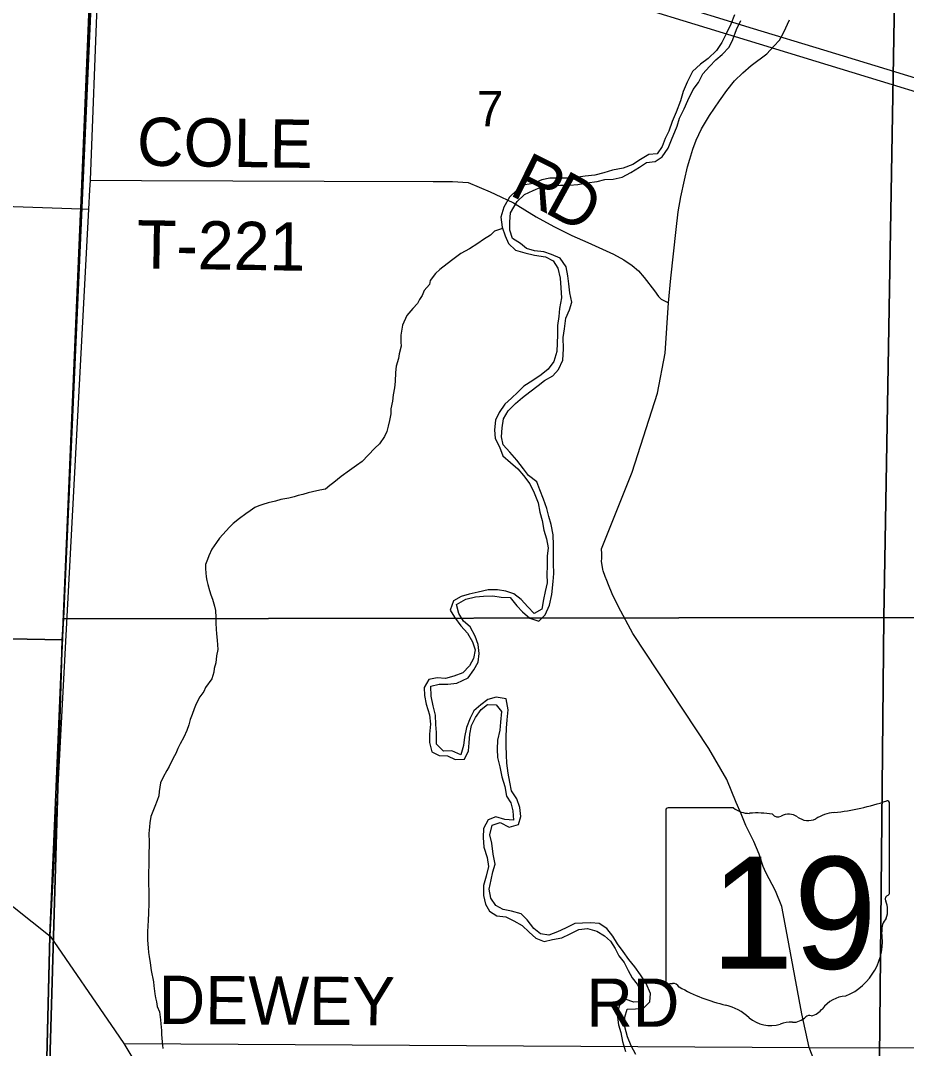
# Model space of a CAD drawing. Extents: x 36.7 to 70.7, y 0 to 22.
# Drawn here: x 41.231 to 42.275, y 17.404 to 18.615 of the extents above; entities that cross this region are included whole.
import ezdxf

# ---------------------------------------------------------------- set-up
doc = ezdxf.new("R2010")
doc.units = 0
for name, color, linetype in [('GM_X_County_Road', 7, 'Continuous'), ('GM_X_County_Road_Text', 7, 'Continuous'), ('GM_X_Minor_River', 7, 'Continuous'), ('GM_X_Rail_Line', 7, 'Continuous'), ('GM_X_Section', 7, 'Continuous'), ('GM_X_Section_Text', 7, 'Continuous'), ('GM_X_State_Location', 7, 'Continuous'), ('GM_X_State_Route', 7, 'Continuous'), ('GM_X_State_Shield', 7, 'Continuous'), ('GM_X_Township_Road', 7, 'Continuous'), ('GM_X_Township_Road_Text', 7, 'Continuous')]:
    doc.layers.add(name, color=color, linetype=linetype)

msp = doc.modelspace()

# ---------------------------------------------------------------- linework, layer by layer
at = {"layer": 'GM_X_County_Road'}
for p, q in [((41.3138, 18.4272), (41.3291, 18.8232)), ((41.3132, 18.4157), (41.3138, 18.4272)), ((41.3119, 18.3928), (41.3132, 18.4157)), ((41.2664, 17.5366), (41.3119, 18.3928)), ((41.2501, 16.8809), (41.2664, 17.5366)), ((41.3531, 17.4104), (42.1609, 17.4056))]:
    msp.add_line(p, q, dxfattribs=at)
for points in [[(40.8318, 18.4101), (40.8294, 18.29), (40.8266, 18.1856), (40.8334, 18.07), (40.8364, 18.021), (40.8467, 17.9741), (40.9906, 17.7663), (41.0943, 17.6731), (41.2664, 17.5366)], [(41.2664, 17.5366), (41.3428, 17.4253), (41.3531, 17.4104)], [(41.3531, 17.4104), (41.5942, 17.0098), (41.7249, 16.7795), (41.7442, 16.7267), (41.7621, 16.6558), (41.8308, 16.4207)], [(42.1609, 17.4056), (42.5156, 17.4053), (43.2502, 17.4045)]]:
    msp.add_lwpolyline(points, dxfattribs=at)
at = {"layer": 'GM_X_Minor_River'}
for points in [[(42.0726, 18.6219), (42.0685, 18.6106), (42.0633, 18.6001), (42.0577, 18.5893), (42.0514, 18.5796), (42.0417, 18.5703), (42.0328, 18.5637), (42.0234, 18.5549), (42.017, 18.5425), (42.0122, 18.5313), (42.0092, 18.5204), (42.0039, 18.5072), (41.9991, 18.4963), (41.9953, 18.4847), (41.9909, 18.4761), (41.9873, 18.4667)], [(41.8787, 18.2942), (41.8775, 18.3049), (41.8762, 18.3144), (41.8742, 18.3251), (41.8673, 18.3352), (41.8572, 18.3396), (41.8482, 18.3425), (41.8372, 18.344), (41.8278, 18.3465), (41.8204, 18.3524), (41.811, 18.3584), (41.8079, 18.3683), (41.8078, 18.3778), (41.8088, 18.3884), (41.8168, 18.4019), (41.8253, 18.41), (41.8353, 18.415), (41.8445, 18.4186), (41.8544, 18.4202), (41.8677, 18.421), (41.8783, 18.4211), (41.8882, 18.4219), (41.8989, 18.4239), (41.9107, 18.4255), (41.9199, 18.4279), (41.9297, 18.4284), (41.9404, 18.4307), (41.9504, 18.4362), (41.9608, 18.4423), (41.9689, 18.4478), (41.9792, 18.449), (41.9873, 18.4545), (41.9944, 18.4646), (41.9985, 18.4747), (42.005, 18.4905), (42.0079, 18.4999), (42.0135, 18.5111), (42.0179, 18.5209), (42.024, 18.534), (42.0303, 18.5422), (42.0355, 18.5523), (42.0433, 18.5608), (42.0507, 18.5686), (42.0581, 18.5752), (42.0663, 18.5837), (42.0707, 18.5927), (42.0752, 18.6043), (42.08, 18.6152)], [(41.9873, 18.4667), (41.9817, 18.4581), (41.9718, 18.4572), (41.9618, 18.4514), (41.953, 18.4456), (41.9415, 18.4413), (41.9289, 18.439), (41.9186, 18.4355), (41.9082, 18.4331), (41.8968, 18.4319), (41.8858, 18.4303), (41.8763, 18.4295), (41.8664, 18.4294), (41.8551, 18.4293), (41.8455, 18.4273), (41.8359, 18.423), (41.8256, 18.4214), (41.8164, 18.4152), (41.8074, 18.4071), (41.801, 18.3951), (41.7973, 18.3834), (41.7989, 18.3716), (41.8024, 18.3616), (41.8063, 18.3524), (41.8148, 18.3446), (41.8257, 18.3413), (41.8371, 18.3387), (41.8499, 18.3368), (41.8592, 18.332), (41.8647, 18.3235), (41.8674, 18.3116), (41.8682, 18.3002), (41.8687, 18.2884), (41.8664, 18.276), (41.8658, 18.2665), (41.864, 18.2559), (41.8641, 18.2449), (41.8638, 18.235), (41.8632, 18.2252), (41.8598, 18.2135), (41.8531, 18.2046), (41.845, 18.1976), (41.8349, 18.191), (41.8245, 18.1845), (41.8175, 18.1775), (41.8101, 18.1701), (41.802, 18.1631), (41.7956, 18.1534), (41.7912, 18.1444), (41.7898, 18.133), (41.7906, 18.1228), (41.7957, 18.1128), (41.7996, 18.1024), (41.8088, 18.0946), (41.8173, 18.0871), (41.824, 18.0793), (41.8316, 18.0693), (41.8367, 18.0589), (41.8413, 18.047), (41.8433, 18.0359), (41.846, 18.0263), (41.848, 18.0149), (41.8511, 18.0046), (41.8531, 17.9942), (41.8521, 17.9844), (41.8518, 17.973), (41.8515, 17.9628), (41.852, 17.9529), (41.8498, 17.9427), (41.8477, 17.9333), (41.8455, 17.9219), (41.8366, 17.9165), (41.8292, 17.9247), (41.8215, 17.9332), (41.8126, 17.9399), (41.8032, 17.9428), (41.7934, 17.9446), (41.7824, 17.9446), (41.7706, 17.9418), (41.7599, 17.9395), (41.7507, 17.9367)], [(41.7994, 18.3701), (41.7899, 18.3671), (41.7853, 18.3622), (41.7769, 18.357), (41.7704, 18.3525), (41.7604, 18.3461), (41.7501, 18.3406), (41.7391, 18.3323), (41.7253, 18.3218), (41.7203, 18.317), (41.7141, 18.3087), (41.7133, 18.3041), (41.7072, 18.297), (41.7048, 18.2913), (41.7017, 18.2864), (41.699, 18.2819), (41.6936, 18.2759), (41.6867, 18.2676), (41.6813, 18.2563), (41.6804, 18.2491), (41.6796, 18.2445), (41.6795, 18.2362), (41.6799, 18.2316), (41.6775, 18.2225), (41.6767, 18.2172), (41.6739, 18.2081), (41.6734, 18.2006), (41.6729, 18.1899), (41.6721, 18.1824), (41.6705, 18.1744), (41.6696, 18.1668), (41.6676, 18.1577), (41.6676, 18.1517), (41.6663, 18.1441), (41.6647, 18.1373), (41.6632, 18.1312), (41.6604, 18.1252), (41.6543, 18.1165), (41.6489, 18.1116), (41.6412, 18.103), (41.6339, 18.0958), (41.6274, 18.091), (41.619, 18.085), (41.6091, 18.0779), (41.6006, 18.0711), (41.5957, 18.0674), (41.5907, 18.0633), (41.5842, 18.0618), (41.5755, 18.06), (41.5705, 18.0589), (41.5641, 18.0567), (41.5584, 18.0557), (41.5538, 18.0542), (41.5477, 18.0527), (41.5382, 18.0509), (41.5317, 18.0491), (41.523, 18.0469), (41.5169, 18.0451), (41.5123, 18.0436), (41.5074, 18.0414), (41.502, 18.0377), (41.497, 18.0339), (41.4894, 18.0287), (41.4821, 18.0227), (41.4775, 18.0182), (41.466, 18.0054), (41.4625, 18.0005), (41.4567, 17.9926), (41.4532, 17.9847), (41.4517, 17.9801), (41.4493, 17.9745), (41.4493, 17.9692), (41.4503, 17.96), (41.451, 17.9555), (41.4521, 17.9509), (41.4539, 17.9437), (41.4557, 17.9387), (41.4576, 17.9334), (41.4601, 17.9254), (41.4612, 17.9201), (41.4615, 17.9121), (41.4614, 17.9053), (41.4621, 17.8984), (41.4624, 17.8927), (41.4631, 17.8851), (41.4637, 17.8741), (41.4625, 17.8669), (41.4617, 17.8586), (41.4597, 17.8521), (41.4593, 17.8476), (41.4569, 17.8396), (41.4492, 17.8295), (41.4472, 17.8249), (41.4426, 17.8185), (41.4383, 17.8102), (41.436, 17.8046), (41.4336, 17.7978), (41.4313, 17.7917), (41.4297, 17.7857), (41.4274, 17.7789), (41.4239, 17.7709)], [(41.7884, 17.6331), (41.7868, 17.6464), (41.7844, 17.656), (41.787, 17.6673), (41.7966, 17.6704), (41.807, 17.6652), (41.8181, 17.6683), (41.821, 17.6777), (41.8198, 17.6884), (41.8163, 17.6984), (41.8101, 17.708), (41.8081, 17.718), (41.8061, 17.7286), (41.8045, 17.7404), (41.804, 17.75), (41.8036, 17.7614), (41.8035, 17.7709), (41.8041, 17.7815), (41.8048, 17.7913), (41.8062, 17.8034), (41.8035, 17.816), (41.7919, 17.8182), (41.7819, 17.8155), (41.7738, 17.8093), (41.7656, 17.8019), (41.7612, 17.7933), (41.7571, 17.7824), (41.7545, 17.7711), (41.7535, 17.7612), (41.7502, 17.7503), (41.7397, 17.7548), (41.7298, 17.7546), (41.7217, 17.7628), (41.7217, 17.7765), (41.7208, 17.786), (41.7204, 17.7971), (41.7176, 17.8081), (41.7153, 17.8192), (41.7148, 17.831), (41.7248, 17.8334), (41.735, 17.8335), (41.7457, 17.8347), (41.7587, 17.8408), (41.7654, 17.8505), (41.7706, 17.8595), (41.772, 17.8697), (41.7708, 17.88), (41.7673, 17.8899), (41.7611, 17.9011), (41.7533, 17.9078), (41.7479, 17.9166), (41.7451, 17.9274), (41.7563, 17.9335), (41.7674, 17.9362), (41.7769, 17.9371), (41.7879, 17.9376), (41.7977, 17.9358), (41.8083, 17.9355), (41.8164, 17.9258), (41.823, 17.9188), (41.8315, 17.9113), (41.8421, 17.9076), (41.8498, 17.915), (41.8547, 17.9266), (41.8573, 17.9391), (41.8589, 17.9542), (41.8599, 17.9637), (41.8594, 17.9755), (41.8594, 17.9865), (41.8593, 17.9971), (41.8592, 18.0093), (41.8565, 18.0215), (41.8541, 18.031), (41.8517, 18.0402), (41.8475, 18.0514), (41.8432, 18.0625), (41.8397, 18.0717), (41.83, 18.0792), (41.8242, 18.0869), (41.8161, 18.0974), (41.808, 18.1067), (41.8003, 18.1153), (41.7983, 18.1248), (41.7989, 18.1355), (41.8004, 18.146), (41.8059, 18.1554), (41.8145, 18.1639), (41.823, 18.1712), (41.8316, 18.1778), (41.8412, 18.1852), (41.849, 18.191), (41.8586, 18.1965), (41.8653, 18.2039), (41.8705, 18.2151), (41.8712, 18.2284), (41.8708, 18.2417), (41.8722, 18.2519), (41.8741, 18.2644), (41.8782, 18.2745), (41.8811, 18.2835), (41.8787, 18.2942)], [(41.7507, 17.9367), (41.7415, 17.9316), (41.7378, 17.9207), (41.7428, 17.9122), (41.7501, 17.9022), (41.7579, 17.8936), (41.764, 17.8832), (41.7672, 17.874), (41.765, 17.8638), (41.7606, 17.8552), (41.7524, 17.847), (41.7421, 17.8428), (41.7321, 17.84), (41.7223, 17.841), (41.7124, 17.839), (41.7072, 17.8297), (41.7073, 17.8202), (41.7093, 17.8099), (41.7132, 17.7973), (41.7144, 17.7862), (41.7133, 17.7745), (41.7134, 17.7646), (41.7162, 17.7539), (41.7248, 17.7495), (41.7346, 17.7492), (41.7436, 17.7448), (41.7546, 17.7452), (41.7594, 17.755), (41.7601, 17.7645), (41.7607, 17.7747), (41.7629, 17.7849), (41.7677, 17.7942), (41.774, 17.8036), (41.7818, 17.8094), (41.792, 17.8091), (41.7982, 17.8014), (41.7971, 17.7889), (41.7961, 17.7794), (41.7935, 17.7677), (41.7929, 17.7571), (41.7933, 17.7472), (41.7961, 17.7361), (41.7984, 17.7243), (41.8019, 17.7128), (41.8039, 17.7017), (41.809, 17.6936), (41.8117, 17.6844), (41.8122, 17.6734), (41.802, 17.6741), (41.7914, 17.6774), (41.7826, 17.6735), (41.777, 17.6634), (41.7764, 17.6528), (41.7772, 17.6413), (41.7814, 17.6295), (41.783, 17.6188), (41.7801, 17.6075), (41.7771, 17.5962), (41.7768, 17.5844), (41.7792, 17.5745), (41.7839, 17.566), (41.7925, 17.5608), (41.8034, 17.5594), (41.8128, 17.5546), (41.8225, 17.5494), (41.8306, 17.5412), (41.8388, 17.5345), (41.8485, 17.5304), (41.8584, 17.5328), (41.8691, 17.5348), (41.8791, 17.5395), (41.8891, 17.5445), (41.8994, 17.5457), (41.9103, 17.5424), (41.9196, 17.5372), (41.9266, 17.5306), (41.9321, 17.5221), (41.9364, 17.5136), (41.9426, 17.5058), (41.9473, 17.4962), (41.952, 17.4877), (41.9579, 17.48), (41.9633, 17.4703), (41.9645, 17.4593), (41.9539, 17.4588), (41.9438, 17.4625), (41.9367, 17.4547), (41.9345, 17.4445), (41.9361, 17.4323), (41.9389, 17.4232), (41.9409, 17.4125), (41.9444, 17.401)], [(41.4239, 17.7709), (41.4196, 17.763), (41.4169, 17.7577), (41.4142, 17.752), (41.4114, 17.7464), (41.4064, 17.7366), (41.4037, 17.7317), (41.3994, 17.7241), (41.3963, 17.7173), (41.3947, 17.7071), (41.3942, 17.7018), (41.3923, 17.6965), (41.3895, 17.6893), (41.3849, 17.6776), (41.3836, 17.67), (41.3832, 17.6655), (41.3827, 17.6575), (41.383, 17.6472), (41.3829, 17.6427), (41.3825, 17.6351), (41.382, 17.5968), (41.3824, 17.5911), (41.3827, 17.5842), (41.3825, 17.5744), (41.3821, 17.5649), (41.3819, 17.5543), (41.3815, 17.5497), (41.381, 17.541), (41.3809, 17.5319), (41.3816, 17.5231), (41.3823, 17.5174), (41.383, 17.5129), (41.384, 17.5053), (41.3854, 17.4961), (41.3879, 17.4828), (41.3886, 17.4783), (41.3897, 17.4688), (41.3904, 17.4642), (41.3915, 17.4593), (41.3925, 17.4539), (41.3951, 17.4475), (41.3965, 17.438), (41.3969, 17.4334), (41.3975, 17.4254), (41.3975, 17.4209), (41.3981, 17.4121), (41.3992, 17.4045)], [(41.854, 17.5379), (41.8442, 17.5393), (41.8364, 17.5456), (41.8284, 17.556), (41.8213, 17.5631), (41.81, 17.566), (41.8002, 17.5682), (41.7913, 17.5726), (41.7854, 17.5815), (41.7838, 17.5922), (41.786, 17.6031), (41.7878, 17.6126), (41.7907, 17.6216), (41.7884, 17.6331)], [(41.9564, 17.3972), (41.951, 17.4076), (41.9467, 17.418), (41.9436, 17.4299), (41.9436, 17.4413), (41.9461, 17.4507), (41.956, 17.4512), (41.9654, 17.4517), (41.9729, 17.4594), (41.9739, 17.4693), (41.9685, 17.4808), (41.962, 17.4912), (41.9554, 17.5005), (41.9484, 17.5091), (41.9415, 17.5188), (41.9349, 17.5277), (41.9295, 17.5366), (41.9221, 17.5459), (41.9132, 17.5514), (41.9033, 17.5525), (41.8938, 17.552), (41.8844, 17.5515), (41.8736, 17.5461), (41.864, 17.5418), (41.854, 17.5379)]]:
    msp.add_lwpolyline(points, dxfattribs=at)
at = {"layer": 'GM_X_Rail_Line'}
for points in [[(39.4351, 19.5275), (39.5072, 19.4857), (39.6526, 19.4084), (39.8435, 19.3143), (39.9823, 19.2538), (40.1053, 19.2054), (40.2394, 19.1588), (40.707, 19.0117), (41.5752, 18.749), (42.4154, 18.492), (43.2547, 18.2349), (44.5058, 17.8517), (44.9515, 17.7199), (45.506, 17.5551), (45.5934, 17.5283)], [(40.4184, 19.1184), (40.5342, 19.0828), (40.5644, 19.0736), (40.633, 19.0526), (40.7242, 19.0248), (40.8662, 18.9816), (41.0703, 18.9191), (41.1118, 18.9063), (41.2352, 18.8682), (41.3301, 18.8394), (41.5595, 18.7692), (41.7245, 18.7187), (41.8299, 18.6867), (41.9106, 18.662), (41.99, 18.6377), (42.0947, 18.6058), (42.1775, 18.5805), (42.2523, 18.5576), (42.4612, 18.4939)]]:
    msp.add_lwpolyline(points, dxfattribs=at)
at = {"layer": 'GM_X_Section'}
for points in [[(41.3255, 18.8876), (41.2819, 17.9105), (41.2806, 17.8858), (40.1915, 17.9066), (40.2272, 18.9664)], [(42.2659, 18.914), (42.2487, 17.912), (41.2819, 17.9105), (41.3255, 18.8876), (41.3264, 18.9176)], [(43.2658, 18.9165), (43.2576, 17.9081), (42.2487, 17.912), (42.2659, 18.914)], [(41.2806, 17.8858), (41.2523, 16.9188), (41.2509, 16.8855), (40.1819, 16.9057), (40.1915, 17.9066)], [(42.2487, 17.912), (42.2388, 16.9146), (41.2523, 16.9188), (41.2806, 17.8858), (41.2819, 17.9105)], [(43.2576, 17.9081), (43.2397, 16.908), (42.2388, 16.9146), (42.2487, 17.912)]]:
    msp.add_lwpolyline(points, close=True, dxfattribs=at)
at = {"layer": 'GM_X_State_Route'}
for points in [[(41.9948, 18.2825), (41.9976, 18.3115), (42.0041, 18.3689), (42.0065, 18.3896), (42.0096, 18.4075), (42.0138, 18.4269), (42.0175, 18.4428), (42.0199, 18.4517), (42.0235, 18.4634), (42.0275, 18.474), (42.0339, 18.4876), (42.0431, 18.5032), (42.055, 18.5204), (42.0638, 18.5325), (42.0728, 18.544), (42.0824, 18.5535), (42.0923, 18.562), (42.1107, 18.5759), (42.1192, 18.5847), (42.1256, 18.5921), (42.1308, 18.6012), (42.1376, 18.616)], [(42.183, 17.3482), (42.1609, 17.4056), (42.1522, 17.4454), (42.1335, 17.5444), (42.1286, 17.5715), (42.1209, 17.5902), (42.1095, 17.6116), (42.1065, 17.6189), (42.1018, 17.6334), (42.0956, 17.6483), (42.086, 17.667), (42.0805, 17.6808), (42.0746, 17.6942), (42.0637, 17.7213), (42.0426, 17.7576), (41.9528, 17.893), (41.9362, 17.9244), (41.9284, 17.9397), (41.9241, 17.9504), (41.9222, 17.9557), (41.9204, 17.9603), (41.9178, 17.9668), (41.9175, 17.9687), (41.9161, 17.9782), (41.9162, 17.9816), (41.9162, 17.9869), (41.916, 17.993), (41.9522, 18.0831), (41.982, 18.1762), (41.9911, 18.2231), (41.9948, 18.2825)]]:
    msp.add_lwpolyline(points, dxfattribs=at)
at = {"layer": 'GM_X_State_Shield'}
for p, q in [((42.0716, 17.6877), (41.9944, 17.6877)), ((42.2555, 17.588), (42.2555, 17.6927)), ((41.9918, 17.6843), (41.9918, 17.4841)), ((42.2554, 17.588), (42.2555, 17.588))]:
    msp.add_line(p, q, dxfattribs=at)
for centre, radius, start, end in [((41.9948, 17.6847), 0.00305, 98.1301, 188.1301), ((42.09, 17.7109), 0.0296, 231.6195, 271.1119), ((42.1615, 17.9605), 0.2796, 275.8445, 288.9065), ((42.2525, 17.6931), 0.00294, 351.8621, 97.738), ((42.0998, 17.5754), 0.1064, 80.4867, 94.9883), ((42.124, 17.6857), 0.00855, 219.7921, 297.1024), ((42.1365, 17.6626), 0.0178, 54.4667, 119.1411), ((42.1595, 17.6943), 0.0214, 233.8562, 294.8282), ((42.1972, 17.6266), 0.0563, 97.3462, 120.7689), ((42.2548, 17.5803), 0.00454, 107.944, 210.337), ((42.2259, 17.5671), 0.0273, 340.033, 23.6496), ((42.2523, 17.5876), 0.00314, 289.6038, 7.7341), ((42.266, 17.5442), 0.0198, 136.8065, 186.9296), ((42.1772, 17.5309), 0.0699, 292.3089, 8.9858), ((41.9948, 17.4837), 0.00308, 171.9584, 258.3066), ((41.9953, 17.5042), 0.0235, 267.339, 280.6039), ((42.0001, 17.4726), 0.00848, 29.7484, 93.2717), ((42.1072, 17.6524), 0.2019, 240.4129, 257.1985), ((42.2067, 17.428), 0.0383, 94.4031, 142.5768), ((42.047, 17.3942), 0.0632, 47.1842, 75.836), ((42.1582, 17.4648), 0.0226, 282.8732, 323.2771), ((42.1153, 17.4716), 0.0401, 230.7004, 286.2918), ((42.1385, 17.4024), 0.0329, 85.6951, 111.2099), ((42.1414, 17.4566), 0.0214, 268.777, 315.5493), ((42.1607, 17.4372), 0.00601, 65.7517, 132.6484)]:
    msp.add_arc(centre, radius, start, end, dxfattribs=at)
at = {"layer": 'GM_X_Township_Road'}
for p, q in [((41.3132, 18.4157), (41.3138, 18.4272)), ((41.3119, 18.3928), (41.3132, 18.4157))]:
    msp.add_line(p, q, dxfattribs=at)
for points in [[(44.0245, 19.8612), (43.3189, 19.8494), (43.2806, 19.8481), (42.7713, 19.8373), (42.3685, 19.83), (42.3137, 19.8294), (42.2762, 19.8294), (41.5623, 19.8154), (41.5546, 19.8154), (41.5474, 19.8155), (41.5405, 19.8156), (41.3671, 19.8162), (41.3623, 19.8162), (41.3441, 19.4051), (41.344, 19.4017), (41.3037, 18.4227), (41.3025, 18.3936), (41.3022, 18.3874), (41.2661, 17.5372), (41.2499, 16.8815)], [(41.1522, 14.4699), (41.174, 14.9671), (41.1745, 14.977), (41.2392, 16.3776), (41.2409, 16.4152), (41.2499, 16.8815), (41.2661, 17.5372), (41.3022, 18.3874), (41.3025, 18.3936), (41.3037, 18.4227), (41.344, 19.4017), (41.3441, 19.4051), (41.3623, 19.8162), (40.8614, 19.8261), (40.8514, 19.8263), (40.7997, 19.8273), (40.7924, 19.8275), (40.7387, 19.8285), (40.7272, 19.8287), (40.1721, 19.8397)], [(41.3138, 18.4272), (41.3741, 18.4268), (41.5891, 18.4258), (41.7177, 18.4253), (41.7406, 18.4255), (41.7587, 18.4241), (41.7849, 18.4134), (41.7906, 18.4107)], [(40.8318, 18.4101), (40.9829, 18.4041), (41.3027, 18.3931), (41.3119, 18.3928)], [(41.7906, 18.4107), (41.8124, 18.4003), (41.8392, 18.3838), (41.8599, 18.3724), (41.8811, 18.3617), (41.8998, 18.3536), (41.9302, 18.34), (41.9423, 18.3332), (41.952, 18.3266), (41.9594, 18.3201), (41.9664, 18.3123), (41.9784, 18.2967), (41.9832, 18.2901), (41.9864, 18.2868), (41.9948, 18.2825)]]:
    msp.add_lwpolyline(points, dxfattribs=at)

# ---------------------------------------------------------------- texts
at = {"layer": 'GM_X_County_Road_Text'}
for s, rotation, p in [('DEWEY', 359.6191, (41.394, 17.4334)), ('RD', 0, (41.898, 17.43))]:
    msp.add_text(s, height=0.05682, rotation=rotation, dxfattribs=at).set_placement(p)
at = {"layer": 'GM_X_Section_Text'}
msp.add_text('7', height=0.0419, rotation=0, dxfattribs=at).set_placement((41.7692, 18.4903))
at = {"layer": 'GM_X_State_Location'}
for s in ['s', 'r']:
    msp.add_text(s, height=0.000189, dxfattribs=at).set_placement((42.1207, 17.5709))
msp.add_text('19', height=0.000189, rotation=0, dxfattribs=at).set_placement((42.073, 17.5571))
at = {"layer": 'GM_X_State_Shield'}
msp.add_text('19', height=0.13184, dxfattribs=at).set_placement((42.0444, 17.4983))
at = {"layer": 'GM_X_Township_Road_Text'}
for s, height, rotation, p in [('COLE', 0.05682, 359.2115, (41.3683, 18.4442)), ('R', 0.0568, 333.6793, (41.8058, 18.4104)), ('D', 0.0568, 331.1796, (41.847, 18.39)), ('T-221', 0.05682, 359.1574, (41.3682, 18.3232))]:
    msp.add_text(s, height=height, rotation=rotation, dxfattribs=at).set_placement(p)

doc.saveas('drawing.dxf')
